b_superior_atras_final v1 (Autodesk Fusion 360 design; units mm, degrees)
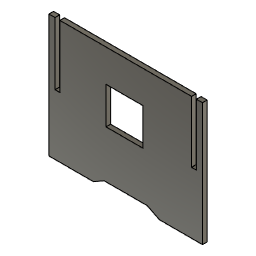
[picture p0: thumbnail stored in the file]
parameter "d10" = 15
parameter "d11" = 0
sketch "Sketch1" plane through (0, 0, 0) normal (0, 1, 0) x axis (1, 0, 0)
  line L1 (500, 0) -> (500, -400)
  line L2 (0, -400) -> (0, 0)
  line L3 (20, -400) -> (0, -400)
  line L4 (20, -200) -> (20, -400)
  line L5 (0, -400) -> (0, -200)
  line L6 (480, -400) -> (500, -400)
  line L7 (480, -200) -> (480, -400)
  line L8 (500, -400) -> (500, -200)
  line L9 (35.75, -196.5937) -> (35.75, -400)
  line L10 (20, -196.5937) -> (35.75, -196.5937)
  line L11 (20, -400) -> (20, -196.5937)
  line L12 (464.25, -200) -> (464.25, -400)
  line L13 (480, -200) -> (464.25, -200)
  line L14 (480, -400) -> (480, -200)
  line L15 (20, -400) -> (0, -400)
  line L16 (464.25, -400) -> (35.75, -400)
  line L17 (500, -400) -> (480, -400)
  line L18 (179.7297, -19.8456) -> (249.7297, -19.9214)
  line L19 (319.7297, -19.9631) -> (249.7297, -19.9214)
  line L20 (360.0001, 0) -> (359.7297, 0)
  line L21 (359.7297, 0) -> (319.7297, -19.9631)
  line L22 (145, 0) -> (179.7297, -19.8456)
  line L23 (359.7297, 0) -> (500, 0)
  line L24 (0, 0) -> (145, 0)
  line L25 (179.7297, -19.8456) -> (319.7297, -19.9631)
  line L26 (-25.0096, -19.6736) -> (0, -19.6946)
  point P24 (359.7297, 0)
  point P25 (145, 0)
  point P26 (0, -19.6946)
  point P2 (0, -400)
  point P3 (500, -400)
  point P5 (0, 0)
  point P6 (20, -400)
  point P8 (0, -200)
  point P9 (480, -400)
  point P11 (500, -200)
  point P12 (35.75, -400)
  point P15 (464.25, -400)
  point P19 (249.7297, -19.9214)
  point P20 (179.7297, -19.8456)
  point P21 (319.7297, -19.9631)
  point P23 (145, 0)
  horizontal L15
  vertical L1
  horizontal L23
  vertical L2
  horizontal L3
  vertical L4
  vertical L5
  horizontal L6
  vertical L7
  vertical L8
  vertical L9
  horizontal L10
  vertical L11
  vertical L12
  horizontal L13
  vertical L14
  collinear L15 L16
  collinear L16 L17
  perpendicular L7 L20
  coincident L21 P24
  coincident L22 P25
  collinear L23 L24
  coincident L2 P26
  collinear L25 L26
  dimension "d1" distance P2 P3 = 500
  dimension "d2" distance P2 P5 = 400
  dimension "d3" distance P2 P6 = 20
  dimension "d4" distance P2 P8 = 200
  dimension "d5" distance P3 P9 = 20
  dimension "d6" distance P3 P11 = 200
  dimension "d7" distance P6 P12 = 15.75
  dimension "d8" distance P9 P15 = 15.75
  dimension "d18" distance P19 P20 = 70
  dimension "d19" distance P19 P21 = 70
  dimension "d26" distance P20 P23 = 40
  dimension "d27" distance P21 P24 = 40
extrude "Extrude3" new body sketch "Sketch1" profile of L17 L1 L24 L2 L3 L4 L5 L6 L7 L8 L9 L10 L11 L12 L13 L14 L18 L19 L20 L21 L22 along normal blind 15
sketch "Sketch4" plane through (0, 15, 0) normal (0, 1, 0) x axis (-1, 0, 0)
  line L1 (-179.7297, 19.8456) -> (-249.7297, 19.9214)
  line L2 (-145, 0) -> (-179.7297, 19.8456)
  line L3 (0, 0) -> (-145, 0)
  line L4 (0, 400) -> (0, 0)
  line L5 (-20, 400) -> (0, 400)
  line L6 (-20, 196.5937) -> (-20, 400)
  line L7 (-35.75, 196.5937) -> (-20, 196.5937)
  line L8 (-35.75, 400) -> (-35.75, 196.5937)
  line L9 (-464.25, 400) -> (-35.75, 400)
  line L10 (-464.25, 200) -> (-464.25, 400)
  line L11 (-480, 200) -> (-464.25, 200)
  line L12 (-480, 400) -> (-480, 200)
  line L13 (-500, 400) -> (-480, 400)
  line L14 (-500, 0) -> (-500, 400)
  line L15 (-359.7297, 0) -> (-500, 0)
  line L16 (-319.7297, 19.9631) -> (-359.7297, 0)
  line L17 (-249.7297, 19.9214) -> (-319.7297, 19.9631)
  line L18 (-185.8449, 294.8156) -> (-305.8449, 294.8156)
  line L19 (-185.8449, 174.8156) -> (-185.8449, 294.8156)
  line L20 (-305.8449, 174.8156) -> (-185.8449, 174.8156)
  line L21 (-305.8449, 294.8156) -> (-305.8449, 174.8156)
  point P19 (-305.8449, 294.8156)
  point P20 (-185.8449, 294.8156)
  point P22 (-305.8449, 174.8156)
  horizontal L18
  vertical L19
  horizontal L20
  vertical L21
  dimension "d36" distance P19 P20 = 120
  dimension "d37" distance P19 P22 = 120
extrude "Extrude4" cut sketch "Sketch4" profile of L18 L19 L20 L21 distance 30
